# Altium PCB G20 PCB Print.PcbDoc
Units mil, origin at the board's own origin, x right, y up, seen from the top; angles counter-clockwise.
Board outline 7101.99 x 6716.29 mil, 2 copper layers (Top Layer, Bottom Layer); 0 components, 0 nets, 220 pads, 0 vias.
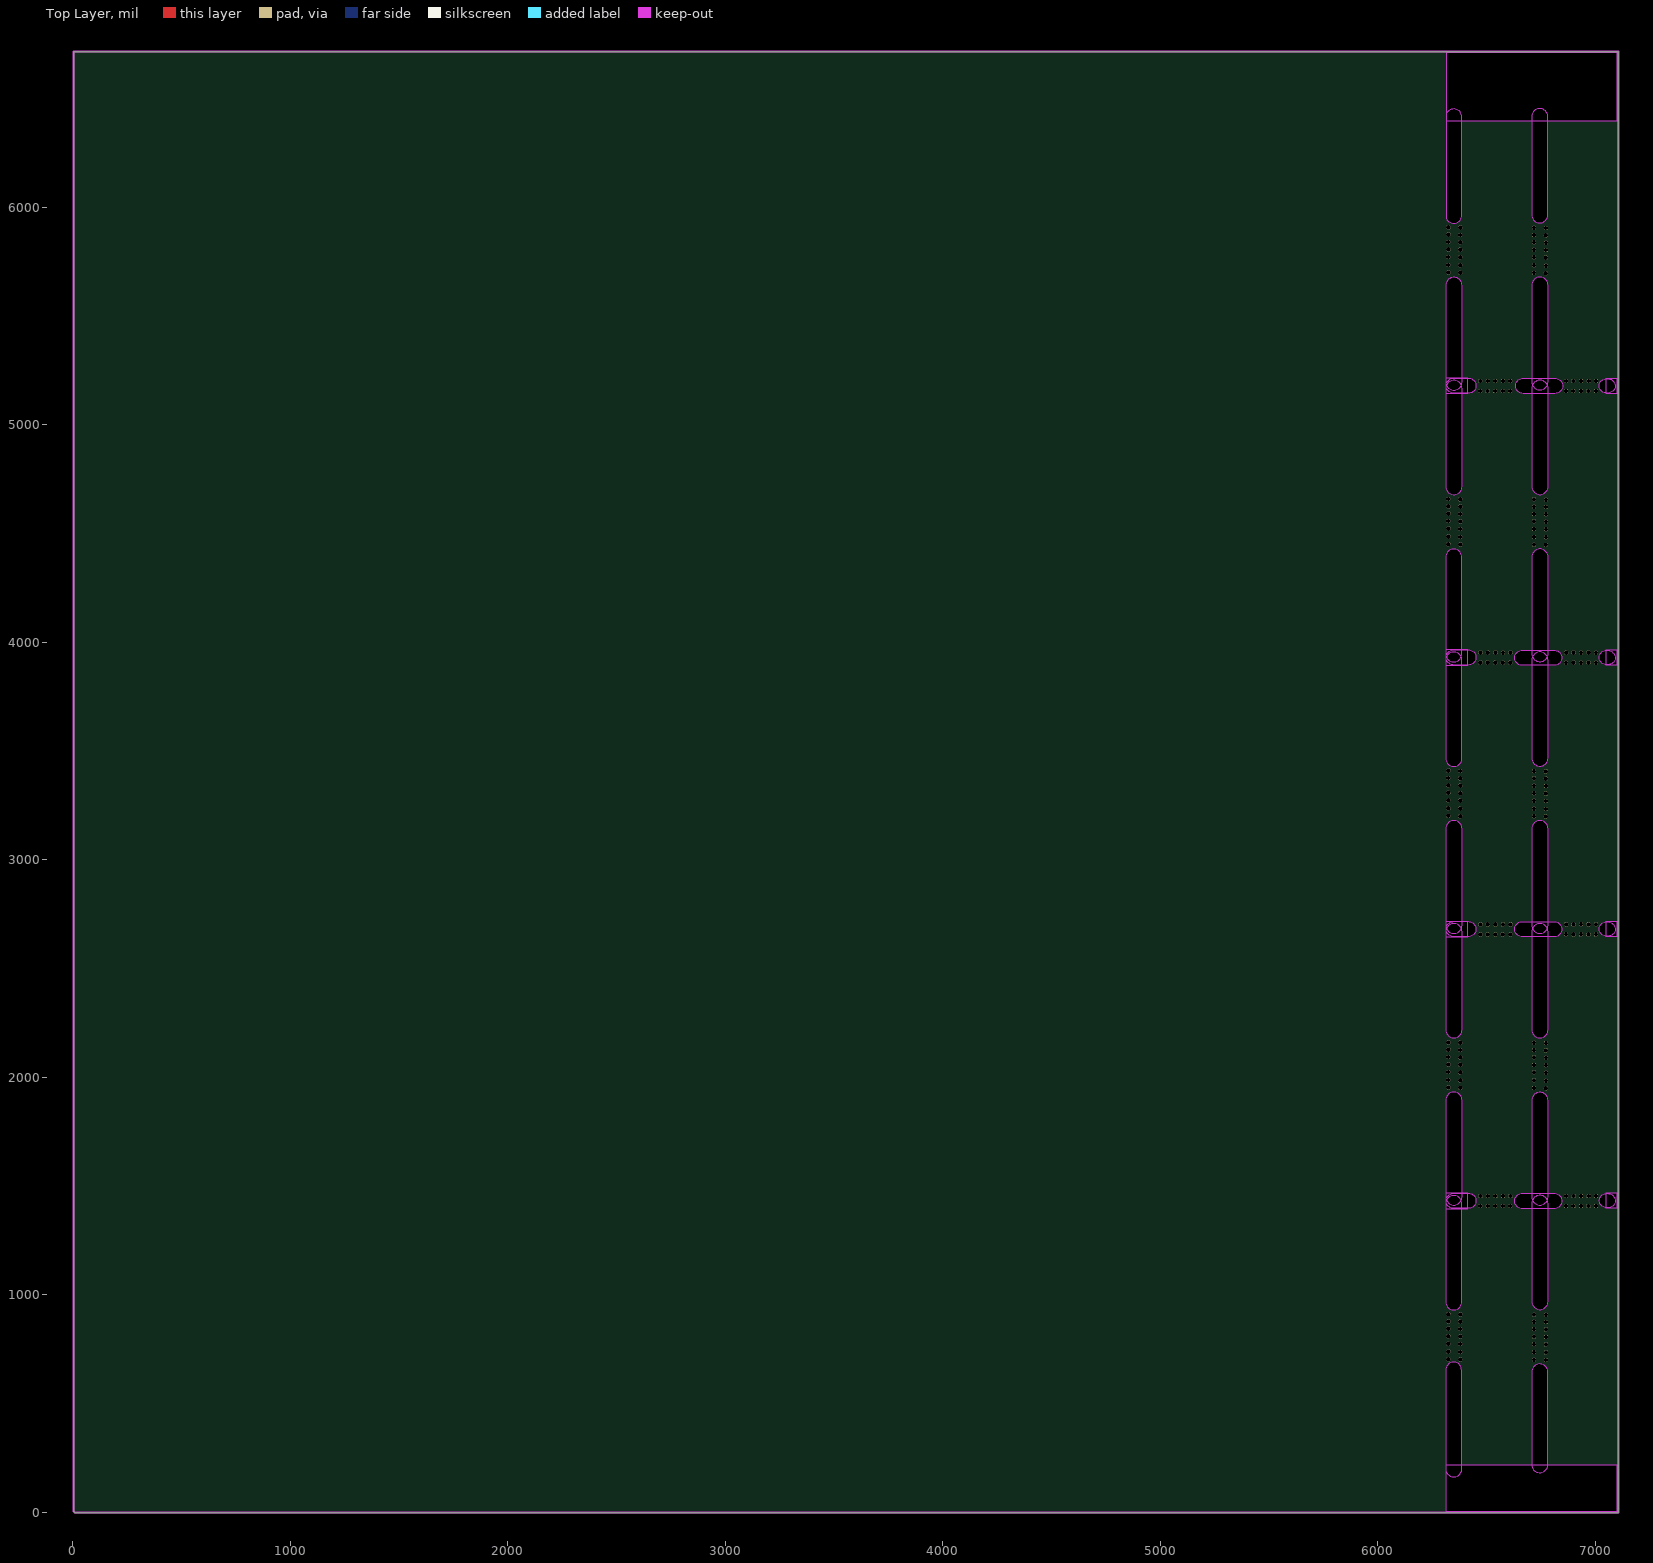
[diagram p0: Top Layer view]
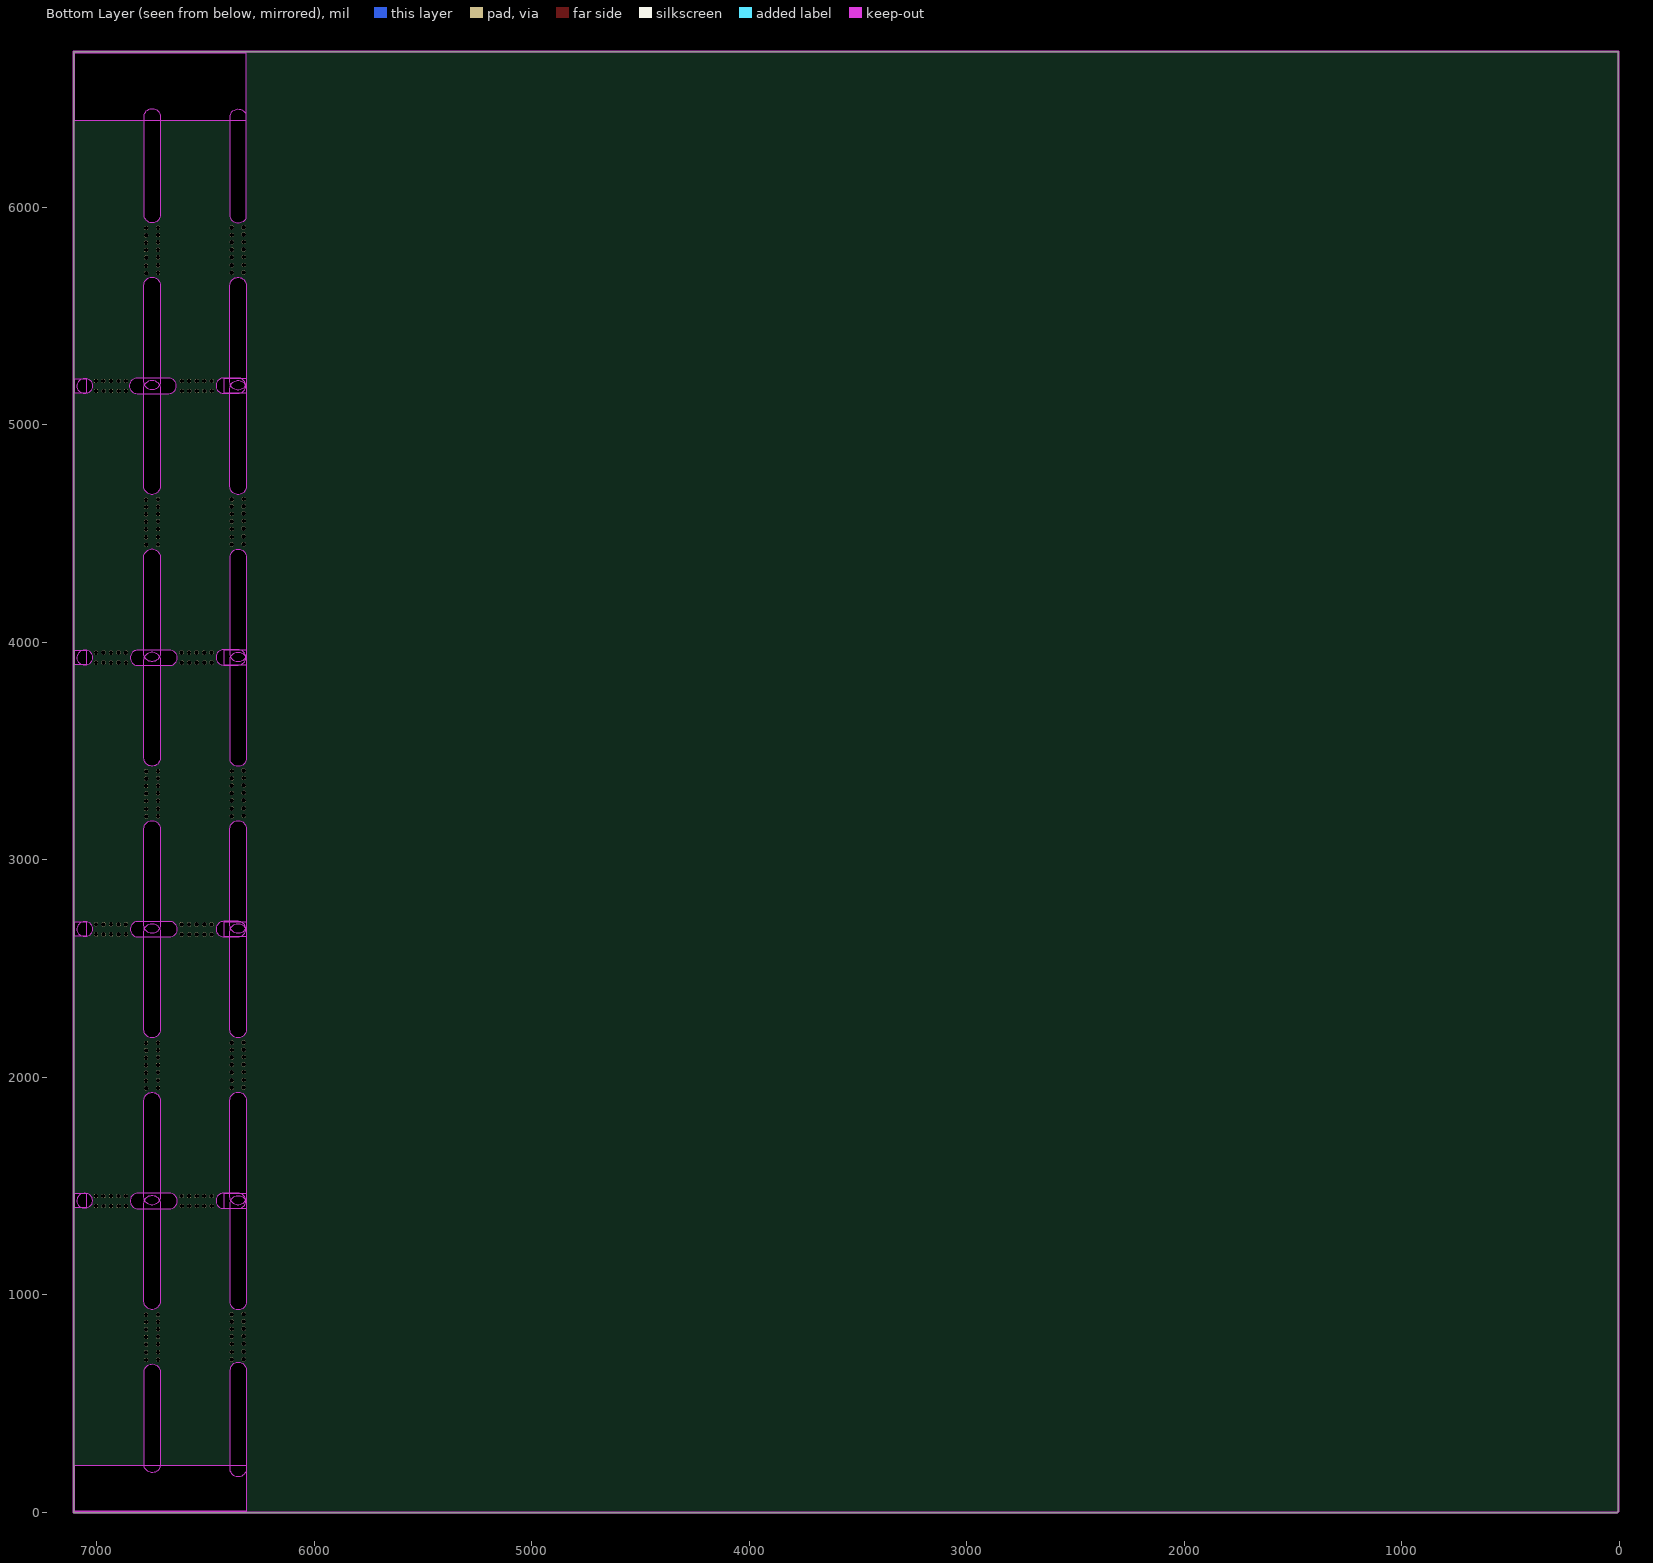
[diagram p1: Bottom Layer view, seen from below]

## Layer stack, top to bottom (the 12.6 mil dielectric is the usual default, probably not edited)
Top Solder: solder mask 0.4, Solder Resist, Dk 3.5
Top Layer: signal copper 1.4
Dielectric 1: dielectric 12.6, FR-4, Dk 4.8
Bottom Layer: signal copper 1.4
Bottom Solder: solder mask 0.4, Solder Resist, Dk 3.5

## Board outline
4.73,5.08 4.73,6716.05 7106.72,6716.05 7106.72,-0.25 11.16,-0.25 5.84,5.08
cut-out: 6315.48,6397.15 7101.72,6397.15 7101.72,6711.05 6315.48,6711.05
cut-out: 7047.54,5146.08 7101.34,5146.08 7101.34,5212.08 7047.54,5212.08
cut-out: 7047.52,3897.41 7101.32,3897.41 7101.32,3963.41 7047.52,3963.41
cut-out: 7047.52,2649.35 7101.32,2649.35 7101.32,2715.35 7047.52,2715.35
cut-out: 7048.22,1400.59 7102.02,1400.59 7102.02,1466.59 7048.22,1466.59
cut-out: 6313.13,4.76 7101.72,4.76 7101.72,217.32 6313.13,217.32
cut-out: 7051.97,1400.73 cw(c7051.97,1433.77) 7051.97,1466.8 7057.11,1466.8 cw(c7057.11,1431.55) 7092.36,1431.55 cw(c7059.33,1433.76) 7057.11,1400.73
cut-out: 7051.27,2649.5 cw(c7051.27,2682.53) 7051.27,2715.56 7056.4,2715.56 cw(c7056.4,2680.31) 7091.65,2680.31 cw(c7058.62,2682.52) 7056.4,2649.5
cut-out: 7051.27,3897.56 cw(c7051.27,3930.59) 7051.27,3963.62 7056.4,3963.62 cw(c7056.41,3928.38) 7091.66,3928.37 cw(c7058.63,3930.59) 7056.4,3897.56
cut-out: 7051.29,5146.23 cw(c7051.29,5179.26) 7051.29,5212.29 7056.42,5212.29 cw(c7056.43,5177.05) 7091.68,5177.04 cw(c7058.65,5179.26) 7056.42,5146.23
cut-out: 6313.46,191.39 ccw(c6349.52,201.02) 6385.2,190.1 6385.2,654.84 ccw(c6349.33,655.49) 6313.46,654.84
cut-out: 6349.95,2646.6 cw(c6349.95,2681.86) 6349.95,2717.11 6416.31,2717.11 cw(c6416.31,2681.86) 6451.57,2681.86 cw(c6416.31,2681.85) 6416.31,2646.6
cut-out: 6664.6,2646.02 cw(c6664.6,2681.27) 6664.6,2716.52 6810.68,2716.52 cw(c6810.68,2681.27) 6845.93,2681.27 cw(c6810.68,2681.27) 6810.68,2646.02
cut-out: 6708.45,2699.31 ccw(c6745.76,2699.31) 6783.08,2699.31 6783.08,3143.51 ccw(c6745.76,3143.51) 6708.45,3143.51
cut-out: 6665.18,1396.91 cw(c6665.18,1432.16) 6665.18,1467.41 6811.26,1467.41 cw(c6811.26,1432.16) 6846.51,1432.16 cw(c6811.26,1432.16) 6811.26,1396.91
cut-out: 6707.34,220.35 ccw(c6744.66,220.35) 6780.55,210.13 6780.55,655.79 ccw(c6744.66,645.57) 6707.34,645.57
cut-out: 6312.45,968.45 ccw(c6349.77,968.45) 6387.09,968.45 6387.09,1419.36 ccw(c6349.77,1419.36) 6312.45,1419.36
cut-out: 6708.62,969.98 ccw(c6745.94,969.98) 6783.26,969.98 6783.26,1420.89 ccw(c6745.94,1420.89) 6708.62,1420.89
cut-out: 6312.94,1450.78 ccw(c6350.26,1450.78) 6387.58,1450.78 6387.58,1894.97 ccw(c6350.26,1894.97) 6312.94,1894.97
cut-out: 6313.07,2218.82 ccw(c6350.39,2218.82) 6387.71,2218.82 6387.71,2669.73 ccw(c6350.39,2669.73) 6313.07,2669.73
cut-out: 6350.07,1397.62 cw(c6350.07,1432.87) 6350.07,1468.12 6416.43,1468.12 cw(c6416.43,1432.87) 6451.68,1432.87 cw(c6416.43,1432.87) 6416.43,1397.62
cut-out: 6708.56,1450.32 ccw(c6745.88,1450.32) 6783.2,1450.32 6783.2,1894.52 ccw(c6745.88,1894.52) 6708.56,1894.52
cut-out: 6708.56,2218.95 ccw(c6745.88,2218.95) 6783.2,2218.95 6783.2,2669.86 ccw(c6745.88,2669.86) 6708.56,2669.86
cut-out: 6312.94,2699.37 ccw(c6350.25,2699.37) 6387.57,2699.37 6387.57,3143.57 ccw(c6350.25,3143.57) 6312.94,3143.57
cut-out: 6312.78,3466.93 ccw(c6350.1,3466.93) 6387.42,3466.93 6387.42,3917.84 ccw(c6350.1,3917.84) 6312.78,3917.84
cut-out: 6708.45,3467.94 ccw(c6745.76,3467.94) 6783.08,3467.94 6783.08,3918.85 ccw(c6745.76,3918.85) 6708.45,3918.85
cut-out: 6312.48,3947.17 ccw(c6349.8,3947.17) 6387.12,3947.17 6387.12,4391.37 ccw(c6349.8,4391.37) 6312.48,4391.37
cut-out: 6312.98,4716.34 ccw(c6350.3,4716.34) 6387.62,4716.34 6387.62,5167.25 ccw(c6350.3,5167.25) 6312.98,5167.25
cut-out: 6350.15,3895.55 cw(c6350.15,3930.81) 6350.15,3966.06 6416.51,3966.06 cw(c6416.51,3930.81) 6451.76,3930.81 cw(c6416.51,3930.81) 6416.51,3895.55
cut-out: 6708.64,3948.26 ccw(c6745.96,3948.26) 6783.28,3948.26 6783.28,4392.46 ccw(c6745.96,4392.46) 6708.64,4392.46
cut-out: 6708.64,4716.89 ccw(c6745.96,4716.89) 6783.28,4716.89 6783.28,5167.8 ccw(c6745.96,5167.8) 6708.64,5167.8
cut-out: 6664.79,3893.83 cw(c6664.79,3929.09) 6664.79,3964.34 6810.88,3964.34 cw(c6810.88,3929.09) 6846.13,3929.09 cw(c6810.88,3929.08) 6810.88,3893.83
cut-out: 6668.78,5143.83 cw(c6668.78,5179.08) 6668.78,5214.33 6814.86,5214.33 cw(c6814.86,5179.08) 6850.11,5179.08 cw(c6814.86,5179.08) 6814.86,5143.83
cut-out: 6707.43,5965.66 ccw(c6744.75,5965.66) 6780.72,5955.72 6780.72,6426.51 ccw(c6744.75,6416.57) 6707.43,6416.57
cut-out: 6708.53,5197.3 ccw(c6745.85,5197.3) 6783.16,5197.3 6783.16,5641.5 ccw(c6745.85,5641.5) 6708.53,5641.5
cut-out: 6350.04,5144.6 cw(c6350.04,5179.85) 6350.04,5215.1 6416.4,5215.1 cw(c6416.4,5179.85) 6451.65,5179.85 cw(c6416.4,5179.85) 6416.4,5144.6
cut-out: 6315.39,5948.89 ccw(c6349.66,5963.66) 6386.98,5963.66 6386.98,6414.57 ccw(c6349.66,6414.57) 6315.39,6429.34
cut-out: 6313.14,5196.66 ccw(c6350.46,5196.66) 6387.77,5196.66 6387.77,5640.86 ccw(c6350.46,5640.86) 6313.14,5640.86
cut-out: 6312.98,5144.37 6412.96,5144.37 6412.96,5214.68 6312.98,5214.68
cut-out: 6312.94,1397.39 6412.99,1397.39 6412.99,1467.7 6312.94,1467.7
cut-out: 6313.34,2646.38 6412.88,2646.38 6412.88,2716.69 6313.34,2716.69
cut-out: 6312.78,3895.33 6413.07,3895.33 6413.07,3965.64 6312.78,3965.64

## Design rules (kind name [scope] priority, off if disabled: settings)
BoardOutlineClearance [All] p1: gap=0 ignorepadtopadclearanceinfootprint=FALSE
Clearance [All] p1: gap=5 ignorepadtopadclearanceinfootprint=FALSE
HoleSize [All] p1: absolutevalues=TRUE maxlimit=100 minlimit=0 maxpercent=80.000 minpercent=20.000
MinimumAnnularRing [All] p1: minimumring=7.09
PolygonConnect [All] p1: connectstyle=Relief reliefconductorwidth=10 reliefentries=4 polygonreliefangle="90 Angle" airgapwidth=10
RoutingVias RoutingVias_1 [All] p1: holewidth=28 width=50 viastyle="Through Hole" minholewidth=28 minwidth=50 maxholewidth=28 maxwidth=50
SolderMaskExpansion [All] p1: expansion=4 istentingtop=FALSE
Width [All] p1: maxlimit=10 minlimit=5 preferedwidth=10 minimp=50.000000 maximp=50.000000 favimp=50.000000
29 further rules are at their usual default settings.

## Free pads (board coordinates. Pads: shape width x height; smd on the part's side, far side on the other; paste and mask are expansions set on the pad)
  round 19.68 hole 19.68 unplated mask+0: 1(6324.17,3342.78) 1(6324.18,3376.41) 1(6324.19,3202.4) 1(6324.19,3273.77) 1(6324.25,3237.12) 1(6324.25,3308.49) 1(6324.25,5840.77) 1(6324.26,5874.4) 1(6324.27,5700.39) 1(6324.27,5771.76) 1(6324.29,2093.79) 1(6324.3,2127.42) 1(6324.3,1953.41) 1(6324.3,2024.78) 1(6324.33,5735.11) 1(6324.33,5806.48) 1(6324.34,844.82) 1(6324.36,878.45) 1(6324.36,1988.13) 1(6324.36,2059.5) 1(6324.36,704.44) 1(6324.36,775.81) 1(6324.37,4591.73) 1(6324.37,3409.98) 1(6324.38,4625.36) 1(6324.38,4451.35) 1(6324.38,4522.72) 1(6324.42,739.16) 1(6324.42,810.53) 1(6324.44,4486.07) 1(6324.44,4557.44) 1(6324.46,5907.97) 1(6324.49,2161) 1(6324.55,912.02) 1(6324.57,4658.93) 1(6378.83,3201.01) 1(6378.85,3375.07) 1(6378.91,5699) 1(6378.93,5873.06) 1(6378.95,1952.02) 1(6378.96,2126.09) 1(6378.97,3408.58) 1(6378.97,3272.4) 1(6378.98,3307.05) 1(6379.01,703.05) 1(6379.02,3235.59) 1(6379.02,877.11) 1(6379.03,4449.96) 1(6379.04,4624.02) 1(6379.05,5906.57) 1(6379.06,5770.39) 1(6379.06,5805.04) 1(6379.09,2159.59) 1(6379.09,2023.41) 1(6379.09,2058.06) 1(6379.1,5733.58) 1(6379.1,3341.31) 1(6379.13,1986.6) 1(6379.15,910.62) 1(6379.15,774.44) 1(6379.15,809.09) 1(6379.17,4657.53) 1(6379.17,4521.35) 1(6379.17,4556) 1(6379.18,5839.31) 1(6379.19,737.63) 1(6379.21,4484.54) 1(6379.22,2092.33) 1(6379.28,843.36) 1(6379.3,4590.26) 1(6471.25,5155.08) 1(6471.46,1408.93) 1(6471.54,3906.54) 1(6471.75,2657.4) 1(6472.28,2703.5) 1(6472.36,5201.49) 1(6472.4,1454.51) 1(6472.48,3952.45) 1(6505.01,5155.17) 1(6505.22,1409.01) 1(6505.3,3906.62) 1(6505.51,2657.49) 1(6506.04,2703.58) 1(6506.12,5201.58) 1(6506.16,1454.6) 1(6506.24,3952.53) 1(6539.72,5155.21) 1(6539.93,1409.05) 1(6540.01,3906.66) 1(6540.22,2657.53) 1(6540.75,2703.62) 1(6540.83,5201.62) 1(6540.86,1454.64) 1(6540.94,3952.58) 1(6574.56,5155.11) 1(6574.77,1408.96) 1(6574.85,3906.57) 1(6575.06,2657.43) 1(6575.58,2703.53) 1(6575.67,5201.52) 1(6575.7,1454.54) 1(6575.78,3952.48) 1(6608.73,5155.11) 1(6608.94,1408.96) 1(6609.02,3906.57) 1(6609.23,2657.43) 1(6609.76,2703.53) 1(6609.84,5201.52) 1(6609.87,1454.54) 1(6609.95,3952.48) 1(6718.14,3340.96) 1(6718.16,3374.59) 1(6718.16,3200.58) 1(6718.16,3271.95) 1(6718.22,3235.3) 1(6718.22,3306.67) 1(6718.22,5838.95) 1(6718.24,5872.58) 1(6718.24,5698.57) 1(6718.24,5769.94) 1(6718.26,2091.97) 1(6718.27,2125.6) 1(6718.28,1951.59) 1(6718.28,2022.96) 1(6718.3,5733.29) 1(6718.3,5804.66) 1(6718.32,843) 1(6718.33,876.63) 1(6718.33,1986.31) 1(6718.33,2057.68) 1(6718.34,702.62) 1(6718.34,773.99) 1(6718.34,4589.91) 1(6718.35,3408.16) 1(6718.35,4623.54) 1(6718.36,4449.53) 1(6718.36,4520.9) 1(6718.39,737.34) 1(6718.39,808.71) 1(6718.41,4484.25) 1(6718.41,4555.62) 1(6718.43,5906.15) 1(6718.46,2159.17) 1(6718.52,910.2) 1(6718.54,4657.11) 1(6772.8,3199.19) 1(6772.82,3373.25) 1(6772.89,5697.18) 1(6772.9,5871.24) 1(6772.92,1950.2) 1(6772.93,2124.26) 1(6772.94,3406.76) 1(6772.95,3270.58) 1(6772.95,3305.23) 1(6772.98,701.23) 1(6772.99,3233.77) 1(6772.99,875.29) 1(6773,4448.14) 1(6773.01,4622.2) 1(6773.03,5904.75) 1(6773.03,5768.57) 1(6773.03,5803.22) 1(6773.06,2157.77) 1(6773.06,2021.59) 1(6773.06,2056.24) 1(6773.07,5731.76) 1(6773.07,3339.49) 1(6773.11,1984.78) 1(6773.12,908.8) 1(6773.12,772.62) 1(6773.12,807.27) 1(6773.14,4655.71) 1(6773.14,4519.53) 1(6773.14,4554.18) 1(6773.16,5837.48) 1(6773.17,735.81) 1(6773.19,4482.72) 1(6773.19,2090.51) 1(6773.25,841.53) 1(6773.27,4588.44) 1(6865.49,2657.6) 1(6865.57,5155.59) 1(6865.6,1408.61) 1(6865.68,3906.55) 1(6866.13,2703.5) 1(6866.21,5201.5) 1(6866.24,1454.52) 1(6866.32,3952.45) 1(6899.25,2657.68) 1(6899.33,5155.67) 1(6899.36,1408.7) 1(6899.44,3906.63) 1(6899.89,2703.59) 1(6899.97,5201.58) 1(6900,1454.6) 1(6900.08,3952.54) 1(6933.96,2657.72) 1(6934.04,5155.72) 1(6934.07,1408.74) 1(6934.15,3906.67) 1(6934.6,2703.63) 1(6934.68,5201.62) 1(6934.71,1454.64) 1(6934.79,3952.58) 1(6968.79,2657.63) 1(6968.87,5155.62) 1(6968.91,1408.64) 1(6968.99,3906.58) 1(6969.43,2703.54) 1(6969.51,5201.53) 1(6969.55,1454.55) 1(6969.63,3952.49) 1(7002.96,2657.63) 1(7003.05,5155.62) 1(7003.08,1408.64) 1(7003.16,3906.58) 1(7003.61,2703.54) 1(7003.69,5201.53) 1(7003.72,1454.55) 1(7003.8,3952.49)

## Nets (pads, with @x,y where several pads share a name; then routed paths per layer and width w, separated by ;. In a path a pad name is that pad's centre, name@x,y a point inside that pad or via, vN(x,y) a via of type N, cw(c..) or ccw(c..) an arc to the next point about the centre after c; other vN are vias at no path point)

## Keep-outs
Keep-Out Layer:
  the board outline again, w10

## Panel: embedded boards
"G20 Braille Reader PCB.PcbDoc" at 9.72,10.16, 1 rows x 1 columns, spacing 2500 x 1500, rotation 0
"Hackaday Braille Cell Source Files\Braille Cell.PcbDoc" at 6395.26,225.46, 5 rows x 2 columns, spacing 1248.74 x 393.97, rotation 0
